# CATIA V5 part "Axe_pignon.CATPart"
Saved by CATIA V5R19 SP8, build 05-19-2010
Part number: Axe_pignon
Revision: ANY
Definition: UNKNOWN
Nomenclature: 17
Source: Unknown
Bounding box of the stored display mesh (mm): x -43.143 to -3.143, y -4 to 4, z -3.991 to 3.991
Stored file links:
  D:\Documents\1_Travail\2- 2I2D\1 - Cours et TD\2- TD\3-TD Assemblage\Pompe AirMan\Axe_pignon.CATPart
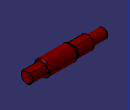
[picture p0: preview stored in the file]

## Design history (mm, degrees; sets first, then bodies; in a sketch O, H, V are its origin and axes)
Body1 "Enlèv. mat.-Extru.2" (main body)
  Solid1: solid without history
